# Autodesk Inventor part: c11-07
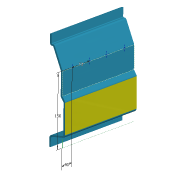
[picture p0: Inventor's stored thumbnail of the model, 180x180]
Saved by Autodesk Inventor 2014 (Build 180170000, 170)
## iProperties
Created: 2011-01
Part Number: c11-07
Material: Aluminum 6061
Document SubType Name: Sheet Metal
Designer: Thom Tremblay
Density: 2.71 g/cm^3
Sheet Metal Rule: Aluminum - 3.4mm
Appearance: Turquoise
Author: Thom Tremblay
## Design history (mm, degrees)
node "Contour Flange1"
  sketch "Sketch1"
    geometry: L1 (0, 0)-(20, 0); L2 (20, 0)-(20, 30); L3 (20, 30)-(90, 30); L4 (100.392, 24)-(150, 24); L5 (150, 24)-(200, 5.801); L6 (200, 5.801)-(200, 0); L7 (200, 0)-(220, 0); L8 (-200, 0)-(-200, 73.265); L9 (90, 30)-(100.392, 24); 1 further point
    constraints: 18 end point, 3 collinear, 3 parallel, 2 perpendicular, 1 coincident, 1 horizontal, 1 horizontal alignment
    dimensions: "d5" = 20 distance of L1.start L1.end; "d6" = 30 distance of L1.end L2.end; "d7" = 70 distance of L2.end L3.end; "d9" = 220 distance of L7.end point (0, 0); "d11" = 20 deg angle of L5 L4; "d12" = 200 distance from line of point (0, 0) L8; "d13" = 6 vertical distance of L3.end L4.start; "d14" = 130 distance from line of L4.end L2; "d15" = 30 deg angle of L9 L3
sketch "Sketch3" dims "d35" = 10
  geometry: L1 (48.12, 0)-(48.12, -300) reference; L2 (0, 0)-(48.12, 0) reference; L3 (0, 0)-(0, -300) reference; L4 (48.12, -300)-(0, -300) reference; L5 (-100.928, -300)-(-100.928, 0) reference; L6 (-100.928, 0)-(-82.928, 0) reference; 4 further points
  constraints: 1 vertical, 3 other
  dimensions: "d28" = 150 distance from line of point (49.072, -40) L5; "d29" = 40 distance from line of L6 point (49.072, -40); "d32" = 73 distance of point (49.072, -40) point (49.072, -113)
body "Solid2"
face "Plate2" dims "d16" = 3.4 (= BendReliefWidth), "d17" = 1.7 (= BendReliefDepth), "d18" = 6.8 (= MinimumRemnant), "d19" = 2 (= BendRadius), "d20" = 300, "d21" = 2 (= BendRadius), "d22" = 3.4, "d23" = 13.6 (= CornerReliefSize), "d24" = 3.4 (= GapSize), "d25" = 2 (= JacobiRadiusSize), "SeamGap" = 0.01, "Thickness" = 3.4 (derived)
bend "Bend1" dims "d16" = 3.4 (= BendReliefWidth), "d17" = 1.7 (= BendReliefDepth), "d18" = 6.8 (= MinimumRemnant), "d19" = 2 (= BendRadius), "d21" = 2 (= BendRadius), "d22" = 3.4, "SeamGap" = 0.01, "Thickness" = 3.4 (derived)
feature "Corner1" dims "d22" = 3.4, "d23" = 13.6 (= CornerReliefSize), "d24" = 3.4 (= GapSize), "d25" = 2 (= JacobiRadiusSize)
other parameters: "BendRadius" = 2 (derived), "BendReliefWidth" = 3.4 (= Thickness), "BendReliefDepth" = 1.7 (= 0.5 x Thickness), "CornerReliefSize" = 13.6 (= 4 x Thickness), "MinimumRemnant" = 6.8 (= 2 x Thickness), "TransitionRadius" = 2 (= BendRadius), "JacobiRadiusSize" = 2 (= BendRadius), "GapSize" = 3.4 (= Thickness), "d4" = 2 (= BendRadius)
